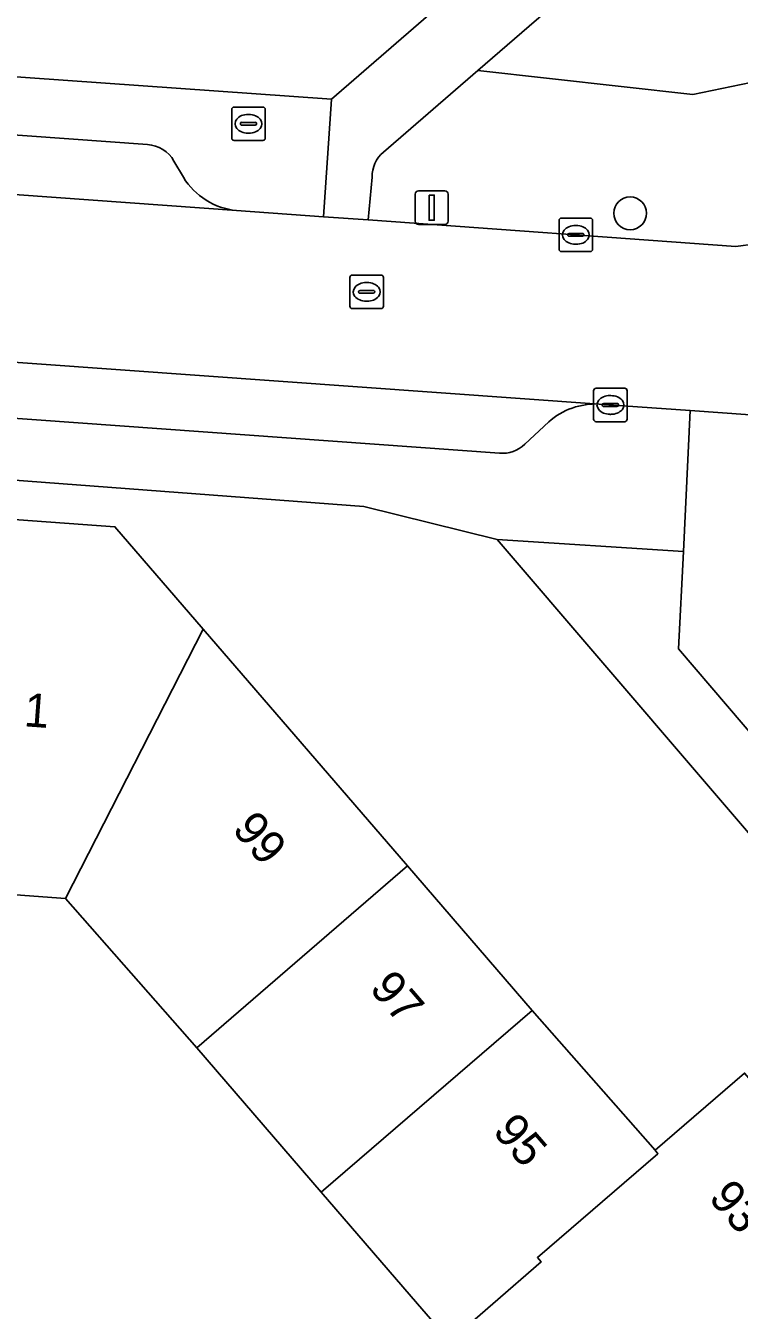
# Model space of a CAD drawing. Extents: x 160304 to 160955, y 383684 to 384161.
# Drawn here: x 160553.09 to 160574.39, y 383999.81 to 384038.14 of the extents above; entities that cross this region are included whole.
import ezdxf

# ---------------------------------------------------------------- set-up
doc = ezdxf.new("R2010")
doc.units = 0
for name, color, linetype in [('IMGEO_Boom', 7, 'Continuous'), ('IMGEO_Brandkraan', 7, 'Continuous'), ('IMGEO_Erf', 7, 'Continuous'), ('IMGEO_Groenvoorziening', 7, 'Continuous'), ('IMGEO_Kolk', 7, 'Continuous'), ('IMGEO_Lichtmast', 7, 'Continuous'), ('IMGEO_Pand', 7, 'Continuous'), ('IMGEO_Pand_nummerreeks', 7, 'Continuous'), ('IMGEO_Parkeervlak_open', 7, 'Continuous'), ('IMGEO_Rijbaan_lokaal_open', 7, 'Continuous'), ('IMGEO_Rioolput', 7, 'Continuous'), ('IMGEO_Voetpad_open', 7, 'Continuous')]:
    doc.layers.add(name, color=color, linetype=linetype)

msp = doc.modelspace()

# ---------------------------------------------------------------- linework, layer by layer
at = {"layer": 'IMGEO_Boom'}
msp.add_circle((160571.128, 384032.544), 0.489, dxfattribs=at)
at = {"layer": 'IMGEO_Brandkraan'}
for p, q in [((160559.241, 384034.789), (160559.241, 384035.641)), ((160559.316, 384035.715), (160560.168, 384035.715)), ((160559.729, 384035.495), (160559.754, 384035.495)), ((160560.242, 384035.641), (160560.242, 384034.789)), ((160559.5, 384035.209), (160559.5, 384035.221)), ((160559.938, 384035.172), (160559.54, 384035.172)), ((160559.543, 384035.258), (160559.941, 384035.258)), ((160559.984, 384035.221), (160559.984, 384035.209)), ((160560.168, 384034.715), (160559.316, 384034.715)), ((160559.752, 384034.935), (160559.727, 384034.935))]:
    msp.add_line(p, q, dxfattribs=at)
for points in [[(160559.241, 384034.789), (160559.241, 384035.641)], [(160559.316, 384035.715), (160560.168, 384035.715)], [(160560.242, 384035.641), (160560.242, 384034.789)], [(160560.168, 384034.715), (160559.316, 384034.715)]]:
    msp.add_lwpolyline(points, dxfattribs=at)
for centre, radius, start, end in [((160559.318, 384035.639), 0.0765, 91.552, 178.448), ((160559.318, 384035.639), 0.0765, 91.552, 178.448), ((160560.166, 384035.639), 0.0765, 1.552, 88.448), ((160560.166, 384035.639), 0.0765, 1.552, 88.448), ((160559.54, 384035.218), 0.0403, 85.8775, 175.7526), ((160559.537, 384035.208), 0.0366, 178.938, 274.7102), ((160559.941, 384035.215), 0.043, 264.8664, 352.4533), ((160559.945, 384035.22), 0.0386, 1.7309, 96.639), ((160559.318, 384034.791), 0.0765, 181.552, 268.448), ((160559.318, 384034.791), 0.0765, 181.552, 268.448), ((160560.166, 384034.791), 0.0765, 271.552, 358.448), ((160560.166, 384034.791), 0.0765, 271.552, 358.448)]:
    msp.add_arc(centre, radius, start, end, dxfattribs=at)
for centre, major_axis, ratio, start_param, end_param in [((160559.728, 384035.215), (-0.387, 0.002), 0.722429, 4.712389, 7.853982), ((160559.753, 384035.215), (-0.39, 0.002), 0.717154, 1.570796, 4.712389)]:
    msp.add_ellipse(centre, major_axis=major_axis, ratio=ratio, start_param=start_param, end_param=end_param, dxfattribs=at)
at = {"layer": 'IMGEO_Erf'}
for points in [[(160575.545, 384053.821), (160571.219, 384050.086), (160566.909, 384046.364), (160559.815, 384040.236), (160550.457, 384040.871), (160544.77, 384041.284), (160539.067, 384041.697), (160533.4, 384042.108), (160527.543, 384042.533), (160527.234, 384038.426), (160562.223, 384035.951), (160577.428, 384049.127)], [(160596.174, 383986.448), (160584.428, 384000), (160576.873, 384008.716), (160576.438, 384011.974), (160567.161, 384022.807), (160563.188, 384023.793), (160526.375, 384026.574), (160526.037, 384022.511), (160531.953, 384022.076), (160537.633, 384021.659), (160543.309, 384021.242), (160548.888, 384020.833), (160552.137, 384020.594), (160552.345, 384023.437), (160555.755, 384023.187), (160558.392, 384020.13), (160564.484, 384013.069), (160568.208, 384008.753), (160571.874, 384004.582), (160574.541, 384006.884), (160578.378, 384002.452), (160580.501, 384000), (160582.098, 383998.155)], [(160565.747, 383998.888), (160564.787, 384000), (160561.911, 384003.332), (160558.196, 384007.637), (160554.286, 384012.093), (160548.348, 384012.529)]]:
    msp.add_lwpolyline(points, dxfattribs=at)
at = {"layer": 'IMGEO_Groenvoorziening'}
for points in [[(160579.344, 384047.835), (160576.201, 384045.119), (160575.882, 384036.684), (160573.001, 384036.092), (160566.582, 384036.805), (160563.766, 384034.371)], [(160563.431, 384033.622), (160563.316, 384032.344), (160574.287, 384031.555), (160576.04, 384031.792), (160577.386, 384032.36)], [(160575.533, 384026.468), (160572.921, 384026.655), (160572.716, 384022.448), (160572.574, 384019.551), (160575.499, 384016.128), (160576.527, 384017.007), (160577.696, 384015.638), (160576.669, 384014.76), (160578.455, 384012.669), (160584.647, 384012.392), (160585.177, 384012.446), (160585.808, 384012.766), (160586.254, 384013.314), (160586.439, 384013.993), (160586.807, 384020.477)]]:
    msp.add_lwpolyline(points, dxfattribs=at)
msp.add_lwpolyline([(160576.201, 384045.119), (160566.582, 384036.805), (160573.001, 384036.092), (160575.882, 384036.684)], close=True, dxfattribs=at)
msp.add_arc((160564.409, 384033.634), 0.978, 131.1001, 180.7055, dxfattribs=at)
at = {"layer": 'IMGEO_Kolk'}
for p, q in [((160569.083, 384032.4), (160569.935, 384032.4)), ((160569.008, 384031.474), (160569.008, 384032.326)), ((160569.496, 384032.18), (160569.521, 384032.18)), ((160570.009, 384032.326), (160570.009, 384031.474)), ((160569.267, 384031.894), (160569.267, 384031.906)), ((160569.705, 384031.857), (160569.307, 384031.857)), ((160569.31, 384031.943), (160569.708, 384031.943)), ((160569.519, 384031.62), (160569.494, 384031.62)), ((160569.751, 384031.906), (160569.751, 384031.894)), ((160569.935, 384031.4), (160569.083, 384031.4)), ((160570.039, 384026.398), (160570.039, 384027.25)), ((160570.114, 384027.324), (160570.966, 384027.324)), ((160570.527, 384027.104), (160570.552, 384027.104)), ((160571.04, 384027.25), (160571.04, 384026.398)), ((160570.298, 384026.818), (160570.298, 384026.83)), ((160570.736, 384026.781), (160570.338, 384026.781)), ((160570.341, 384026.867), (160570.739, 384026.867)), ((160570.782, 384026.83), (160570.782, 384026.818)), ((160570.966, 384026.324), (160570.114, 384026.324)), ((160570.55, 384026.544), (160570.525, 384026.544))]:
    msp.add_line(p, q, dxfattribs=at)
for points in [[(160569.083, 384032.4), (160569.935, 384032.4)], [(160569.008, 384031.474), (160569.008, 384032.326)], [(160570.009, 384032.326), (160570.009, 384031.474)], [(160569.935, 384031.4), (160569.083, 384031.4)], [(160570.039, 384026.398), (160570.039, 384027.25)], [(160570.114, 384027.324), (160570.966, 384027.324)], [(160571.04, 384027.25), (160571.04, 384026.398)], [(160570.966, 384026.324), (160570.114, 384026.324)]]:
    msp.add_lwpolyline(points, dxfattribs=at)
for centre, radius, start, end in [((160569.085, 384032.324), 0.0765, 91.552, 178.448), ((160569.085, 384032.324), 0.0765, 91.552, 178.448), ((160569.933, 384032.324), 0.0765, 1.552, 88.448), ((160569.933, 384032.324), 0.0765, 1.552, 88.448), ((160569.307, 384031.903), 0.0403, 85.8775, 175.7526), ((160569.304, 384031.893), 0.0366, 178.938, 274.7102), ((160569.708, 384031.9), 0.043, 264.8664, 352.4533), ((160569.712, 384031.905), 0.0386, 1.7309, 96.639), ((160569.085, 384031.476), 0.0765, 181.552, 268.448), ((160569.085, 384031.476), 0.0765, 181.552, 268.448), ((160569.933, 384031.476), 0.0765, 271.552, 358.448), ((160569.933, 384031.476), 0.0765, 271.552, 358.448), ((160570.116, 384027.248), 0.0765, 91.552, 178.448), ((160570.116, 384027.248), 0.0765, 91.552, 178.448), ((160570.964, 384027.248), 0.0765, 1.552, 88.448), ((160570.964, 384027.248), 0.0765, 1.552, 88.448), ((160570.338, 384026.827), 0.0403, 85.8775, 175.7526), ((160570.335, 384026.817), 0.0366, 178.938, 274.7102), ((160570.739, 384026.824), 0.043, 264.8664, 352.4533), ((160570.743, 384026.829), 0.0386, 1.7309, 96.639), ((160570.116, 384026.4), 0.0765, 181.552, 268.448), ((160570.116, 384026.4), 0.0765, 181.552, 268.448), ((160570.964, 384026.4), 0.0765, 271.552, 358.448), ((160570.964, 384026.4), 0.0765, 271.552, 358.448)]:
    msp.add_arc(centre, radius, start, end, dxfattribs=at)
for centre, major_axis, ratio, start_param, end_param in [((160569.495, 384031.9), (-0.387, 0.002), 0.722429, 4.712389, 7.853982), ((160569.52, 384031.9), (-0.39, 0.002), 0.717154, 1.570796, 4.712389), ((160570.526, 384026.824), (-0.387, 0.002), 0.722429, 4.712389, 7.853982), ((160570.551, 384026.824), (-0.39, 0.002), 0.717154, 1.570796, 4.712389)]:
    msp.add_ellipse(centre, major_axis=major_axis, ratio=ratio, start_param=start_param, end_param=end_param, dxfattribs=at)
at = {"layer": 'IMGEO_Lichtmast'}
for p, q in [((160564.812, 384033.211), (160565.602, 384033.211)), ((160565.602, 384033.211), (160564.812, 384033.211)), ((160564.712, 384032.311), (160564.712, 384033.111)), ((160564.712, 384033.111), (160564.712, 384032.311)), ((160565.702, 384033.111), (160565.702, 384032.311)), ((160565.702, 384032.311), (160565.702, 384033.111)), ((160565.602, 384032.211), (160564.812, 384032.211)), ((160564.812, 384032.211), (160565.602, 384032.211))]:
    msp.add_line(p, q, dxfattribs=at)
msp.add_lwpolyline([(160565.132, 384033.086), (160565.282, 384033.086), (160565.282, 384032.336), (160565.132, 384032.336), (160565.132, 384033.086)], dxfattribs=at)
for centre, start, end in [((160564.812, 384033.111), 90, 180), ((160564.812, 384033.111), 90, 180), ((160565.602, 384033.111), 0, 90), ((160565.602, 384033.111), 360, 90), ((160564.812, 384032.311), 180, 270), ((160564.812, 384032.311), 180, 270), ((160565.602, 384032.311), 270, 0), ((160565.602, 384032.311), 270, 0)]:
    msp.add_arc(centre, 0.1, start, end, dxfattribs=at)
at = {"layer": 'IMGEO_Pand'}
for points in [[(160548.888, 384020.833), (160548.348, 384012.529), (160554.286, 384012.093), (160558.392, 384020.13), (160555.755, 384023.187), (160552.345, 384023.437), (160552.137, 384020.594)], [(160558.196, 384007.637), (160564.484, 384013.069), (160558.392, 384020.13), (160554.286, 384012.093)], [(160558.196, 384007.637), (160561.911, 384003.332), (160568.208, 384008.753), (160564.484, 384013.069)], [(160565.747, 383998.888), (160567.029, 384000), (160568.47, 384001.25), (160568.36, 384001.38), (160571.96, 384004.48), (160571.874, 384004.582), (160568.208, 384008.753), (160561.911, 384003.332), (160564.787, 384000)], [(160572.091, 383997.052), (160575.523, 384000), (160578.378, 384002.452), (160574.541, 384006.884), (160571.874, 384004.582), (160571.96, 384004.48), (160568.36, 384001.38), (160568.47, 384001.25), (160567.029, 384000), (160565.747, 383998.888), (160569.367, 383994.694)]]:
    msp.add_lwpolyline(points, close=True, dxfattribs=at)
at = {"layer": 'IMGEO_Parkeervlak_open'}
for points in [[(160556.726, 384034.597), (160529.655, 384036.545)], [(160526.85, 384034.98), (160539.053, 384034.09), (160541.846, 384033.889), (160559.384, 384032.627)], [(160557.8, 384033.617), (160557.519, 384034.102)], [(160570.205, 384026.85), (160541.488, 384028.906), (160538.695, 384029.106), (160525.582, 384030.043)], [(160528.12, 384028.197), (160567.23, 384025.383)], [(160567.984, 384025.649), (160568.699, 384026.316)]]:
    msp.add_lwpolyline(points, dxfattribs=at)
for centre, radius, start, end in [((160556.655, 384033.601), 0.999, 30.1228, 85.9314), ((160559.575, 384034.694), 2.076, 211.2571, 264.7321), ((160570.104, 384024.744), 2.109, 87.2603, 131.7868), ((160567.304, 384026.376), 0.995, 265.7501, 313.114)]:
    msp.add_arc(centre, radius, start, end, dxfattribs=at)
at = {"layer": 'IMGEO_Rijbaan_lokaal_open'}
msp.add_lwpolyline([(160587.027, 384029.795), (160577.386, 384032.36), (160576.04, 384031.792), (160574.287, 384031.555), (160563.316, 384032.344), (160561.983, 384032.44), (160559.384, 384032.627), (160541.846, 384033.889), (160541.488, 384028.906), (160570.205, 384026.85), (160572.921, 384026.655), (160575.533, 384026.468)], dxfattribs=at)
at = {"layer": 'IMGEO_Rioolput'}
for p, q in [((160562.767, 384029.773), (160562.767, 384030.625)), ((160562.842, 384030.699), (160563.694, 384030.699)), ((160563.255, 384030.479), (160563.28, 384030.479)), ((160563.768, 384030.625), (160563.768, 384029.773)), ((160563.026, 384030.193), (160563.026, 384030.205)), ((160563.464, 384030.156), (160563.066, 384030.156)), ((160563.069, 384030.242), (160563.467, 384030.242)), ((160563.51, 384030.205), (160563.51, 384030.193)), ((160563.278, 384029.919), (160563.253, 384029.919)), ((160563.694, 384029.699), (160562.842, 384029.699))]:
    msp.add_line(p, q, dxfattribs=at)
for points in [[(160562.767, 384029.773), (160562.767, 384030.625)], [(160562.842, 384030.699), (160563.694, 384030.699)], [(160563.768, 384030.625), (160563.768, 384029.773)], [(160563.694, 384029.699), (160562.842, 384029.699)]]:
    msp.add_lwpolyline(points, dxfattribs=at)
for centre, radius, start, end in [((160562.844, 384030.623), 0.0765, 91.552, 178.448), ((160562.844, 384030.623), 0.0765, 91.552, 178.448), ((160563.692, 384030.623), 0.0765, 1.552, 88.448), ((160563.692, 384030.623), 0.0765, 1.552, 88.448), ((160563.066, 384030.202), 0.0403, 85.8775, 175.7526), ((160563.063, 384030.192), 0.0366, 178.938, 274.7102), ((160563.467, 384030.199), 0.043, 264.8664, 352.4533), ((160563.471, 384030.204), 0.0386, 1.7309, 96.639), ((160562.844, 384029.775), 0.0765, 181.552, 268.448), ((160562.844, 384029.775), 0.0765, 181.552, 268.448), ((160563.692, 384029.775), 0.0765, 271.552, 358.448), ((160563.692, 384029.775), 0.0765, 271.552, 358.448)]:
    msp.add_arc(centre, radius, start, end, dxfattribs=at)
for centre, major_axis, ratio, start_param, end_param in [((160563.254, 384030.199), (-0.387, 0.002), 0.722429, 4.712389, 7.853982), ((160563.279, 384030.199), (-0.39, 0.002), 0.717154, 1.570796, 4.712389)]:
    msp.add_ellipse(centre, major_axis=major_axis, ratio=ratio, start_param=start_param, end_param=end_param, dxfattribs=at)
at = {"layer": 'IMGEO_Voetpad_open'}
for points in [[(160598.394, 384066.298), (160631.761, 384095.048), (160630.096, 384096.946), (160594.287, 384066.063), (160590.891, 384063.065), (160577.514, 384051.539), (160577.428, 384049.127), (160562.223, 384035.951), (160561.983, 384032.44), (160563.316, 384032.344), (160563.431, 384033.622)], [(160563.766, 384034.371), (160566.582, 384036.805), (160576.201, 384045.119), (160579.344, 384047.835)], [(160562.223, 384035.951), (160527.234, 384038.426), (160523.822, 384038.679), (160520.333, 384038.909), (160518.569, 384038.999), (160500, 384040.365), (160485.928, 384041.4)], [(160529.655, 384036.545), (160556.726, 384034.597)], [(160559.384, 384032.627), (160561.983, 384032.44), (160562.223, 384035.951)], [(160557.519, 384034.102), (160557.8, 384033.617)], [(160525.582, 384030.043), (160523.351, 384030.205), (160523.314, 384029.707), (160521.414, 384029.843), (160521.202, 384026.61), (160522.919, 384026.511), (160526.375, 384026.574), (160563.188, 384023.793), (160567.161, 384022.807), (160572.716, 384022.448), (160572.921, 384026.655)], [(160567.23, 384025.383), (160528.12, 384028.197)], [(160572.921, 384026.655), (160570.205, 384026.85)], [(160568.699, 384026.316), (160567.984, 384025.649)], [(160617.179, 383966.719), (160616.269, 383967.769), (160601.248, 383985.099), (160609.035, 383994.079), (160605.836, 383997.776), (160597.474, 383987.879), (160587.067, 384000), (160578.729, 384009.705), (160578.455, 384012.669), (160576.669, 384014.76), (160575.499, 384016.128), (160572.574, 384019.551), (160572.716, 384022.448), (160567.161, 384022.807), (160576.438, 384011.974), (160576.873, 384008.716), (160584.428, 384000), (160596.174, 383986.448), (160599.096, 383983.036), (160637.034, 383939.15), (160638.073, 383937.196), (160638.701, 383936.015), (160653.56, 383908.079), (160657.72, 383910.303)]]:
    msp.add_lwpolyline(points, dxfattribs=at)
for centre, radius, start, end in [((160556.655, 384033.601), 0.999, 30.1228, 85.9314), ((160564.409, 384033.634), 0.978, 131.1001, 180.7055), ((160559.575, 384034.694), 2.076, 211.2571, 264.7321), ((160570.104, 384024.744), 2.109, 87.2603, 131.7868), ((160567.304, 384026.376), 0.995, 265.7501, 313.114)]:
    msp.add_arc(centre, radius, start, end, dxfattribs=at)

# ---------------------------------------------------------------- texts
at = {"layer": 'IMGEO_Pand_nummerreeks'}
for s, rotation, p in [('1', 355.7696, (160553.022, 384017.238)), ('99', 310.7839, (160559.224, 384014.144)), ('97', 310.7888, (160563.322, 384009.394)), ('95', 310.786, (160566.998, 384005.134)), ('93', 310.8843, (160573.439, 384003.146))]:
    msp.add_text(s, height=1, rotation=rotation, dxfattribs=at).set_placement(p)

doc.saveas('drawing.dxf')
